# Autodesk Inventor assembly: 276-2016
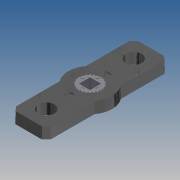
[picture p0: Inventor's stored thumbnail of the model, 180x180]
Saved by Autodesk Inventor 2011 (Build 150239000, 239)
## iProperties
Company: Autodesk Inc.
Created: 2010-06
Part Number: 276-2016
Document SubType Name: Assembly
Designer: Autodesk Inc.
Catalog Web Link: http://www.vexrobotics.com/276-2016.html
Vendor: Innovation First, Inc.
Author: Autodesk Inc.
Title: VEX Robotics Kit of Parts
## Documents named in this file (3)
- C:\Data Folder\VEX KOP 2010\Shaft Lock Bar.iam
- C:\Data Folder\VEX KOP 2010\Shaft Lock Bar.ipt
- C:\Data Folder\VEX KOP 2010\Shaft Lock Bar Insert.ipt
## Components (2 placed, 2 different names)
1. Shaft Lock Bar:1 — Flush:1
2. Shaft Lock Bar Insert:1 — Flush:1
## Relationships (1: Flush 1)
- Flush:1: Shaft Lock Bar:1 ↔ Shaft Lock Bar Insert:1
